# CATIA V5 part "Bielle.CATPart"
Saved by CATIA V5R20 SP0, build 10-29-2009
Part number: Bielle
Bounding box of the stored display mesh (mm): x -16 to -10, y 21.957 to 158.743, z 14.895 to 74.892
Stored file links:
  D:\Dropbox\IAO_2011\MMS_GR2\IAO_2011_1495_fpittorino\fpittorino_IAO\IAO_2011_1495_fpittorino\Bielle.CATPart
  D:\Dropbox\IAO_2011\MMS_GR2\IAO_2011_1495_fpittorino\fpittorino_IAO\IAO_2011_1495_fpittorino\Product3.CATProduct
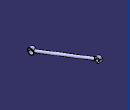
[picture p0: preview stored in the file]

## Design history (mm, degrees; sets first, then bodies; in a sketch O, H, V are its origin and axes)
Set1
  Plane1: linked copy from another document
  Point1: linked copy from another document
  Line1: linked copy from another document
  Point2: linked copy from another document
Body1 (main body)
  Plane2: type Offset, RefPlane Plane1, Offset 16, reversed
  Sketch1 on Plane2, origin (-16, 27.9533, 20.8909), H (0, -0.9318, -0.363), V (0, -0.363, 0.9318)
    circle A1 centre (0, 0) radius 5
    circle A2 centre (-135, 0) radius 2.5
    point P1 (-135, 0)
    reference projected point E1 (-135, 0) from Point2
    circle A3 centre (0, 0) radius 6
    circle A4 centre (-135, 0) radius 5
    radius A2 = 2.5
    radius A1 = 5
    radius A3 = 6
    radius A4 = 5
    coincidence: P1 H, P1 E1
  Pad1: profile Sketch1, direction (1, 0, 0), length 6
  Plane3: type Offset, RefPlane start face of Pad1, Offset 3
  Sketch2 on Plane3, origin (-13, 27.9533, 20.8909), H (0, -0.9318, -0.363), V (0, -0.363, 0.9318)
    line L1 (0, 0) -> (-135, 0)
    line L2 (-135, 0) -> (-135, 2.5)
    line L3 (-135, 2.5) -> (0, 2.5)
    line L4 (0, 2.5) -> (0, 0)
    reference projected point E1 (-135, 0) from Point2
    length L4 = 2.5
    horizontal: L1 H, L3 H
    vertical: L2 V, L4 V
    coincidence: L2 E1
  Shaft1: profile Sketch2, axis Sketch2.L1, angle 360
  Fillet1: radius 0.3, on edge [face of Pad1 from Sketch1.A3 | face of Shaft1 from Sketch2.L3]; edge [face of Shaft1 from Sketch2.L3 | face of Pad1 from Sketch1.A4]
  Point3: type Center, Curve edge [start face of Pad1 | face of Pad1 from Sketch1.A2]
  Sketch3 on start face of Pad1, origin (-16, 160.3445, 48.9184), H (0, 1, 0), V (0, 0, -1)
    point P1 (-6.6013, -20.9816)
    reference projected point E1 (-6.6013, -20.9816) from Point3
    coincidence: E1 P1
  Hole1: placed by Sketch3, at (-16, 153.7432, 69.9) direction (1, 0, 0), diameter 6, through (limit type 6)
  Point4: type Center, Curve edge [start face of Pad1 | face of Pad1 from Sketch1.A1]
  Sketch4 on start face of Pad1, origin (-16, 29.1535, 17.0761), H (0, 1, 0), V (0, 0, -1)
    point P1 (-1.2002, -3.8148)
    reference projected point E1 (-1.2002, -3.8148) from Point4
    coincidence: E1 P1
  Hole2: placed by Sketch4, at (-16, 27.9533, 20.8909) direction (1, 0, 0), diameter 10, through (limit type 6)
